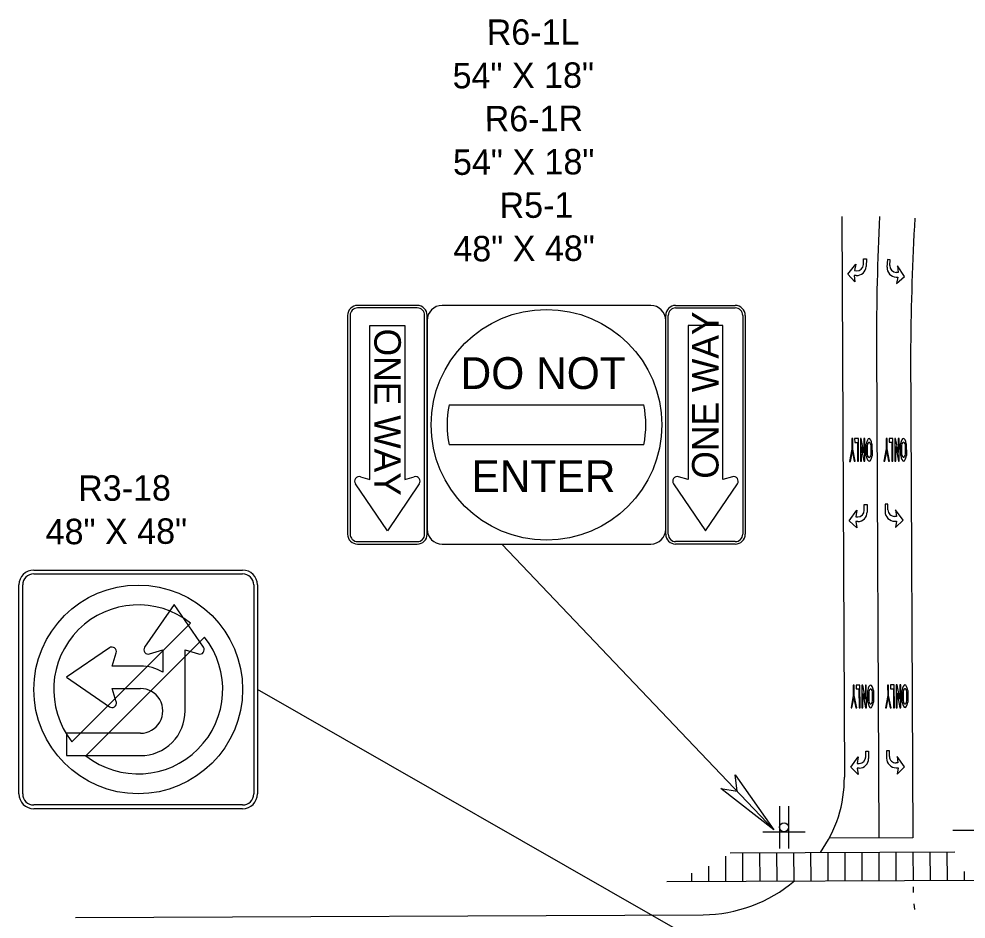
# Model space of a CAD drawing. Extents: x 582908 to 586039, y 1530940 to 1532988.
# Drawn here: x 583214 to 583736, y 1532489 to 1532984 of the extents above; entities that cross this region are included whole.
import ezdxf

# ---------------------------------------------------------------- set-up
doc = ezdxf.new("R2010")
doc.units = 0
for name, color, linetype in [('DirArrowsPavt', 7, 'Continuous'), ('LeaderLine_dp', 7, 'Continuous'), ('PavtMessage', 7, 'Continuous'), ('PMStripe12W', 7, 'Continuous'), ('PMStripe24W', 7, 'Continuous'), ('PMStripe6Y(2-4)', 7, 'Continuous'), ('PMStripe8W', 7, 'Continuous'), ('PMStripe8Y', 7, 'Continuous'), ('SignPanel', 7, 'Continuous'), ('SignSupport', 7, 'Continuous'), ('TextLabel', 7, 'Continuous')]:
    doc.layers.add(name, color=color, linetype=linetype)

msp = doc.modelspace()

# ---------------------------------------------------------------- linework, layer by layer
at = {"layer": 'DirArrowsPavt'}
for p, q in [((583679.03, 1532849.19), (583679.18, 1532852.31)), ((583679.18, 1532852.31), (583680.74, 1532852.23)), ((583680.74, 1532852.23), (583680.54, 1532848.07)), ((583692.22, 1532851.83), (583692.02, 1532847.67)), ((583693.78, 1532851.76), (583692.22, 1532851.83)), ((583693.63, 1532848.63), (583693.78, 1532851.76)), ((583670.44, 1532843.86), (583674.87, 1532849.38)), ((583674.87, 1532849.38), (583674.18, 1532845.77)), ((583674.18, 1532845.77), (583675.22, 1532845.72)), ((583698.14, 1532844.77), (583697.1, 1532844.82)), ((583701.69, 1532842.52), (583697.8, 1532848.44)), ((583697.8, 1532848.44), (583698.14, 1532844.77)), ((583674.41, 1532839.63), (583670.44, 1532843.86)), ((583675.09, 1532843.12), (583674.05, 1532843.17)), ((583674.05, 1532843.17), (583674.41, 1532839.63)), ((583696.98, 1532842.22), (583698.02, 1532842.17)), ((583697.33, 1532838.68), (583701.69, 1532842.52)), ((583698.02, 1532842.17), (583697.33, 1532838.68)), ((583679.55, 1532714.02), (583679.54, 1532717.15)), ((583679.54, 1532717.15), (583681.1, 1532717.15)), ((583681.1, 1532717.15), (583681.12, 1532712.99)), ((583692.55, 1532717.35), (583690.98, 1532717.34)), ((583690.98, 1532717.34), (583691, 1532713.17)), ((583692.56, 1532714.22), (583692.55, 1532717.35)), ((583700.92, 1532708.53), (583696.73, 1532714.24)), ((583696.73, 1532714.24), (583697.26, 1532710.59)), ((583671.24, 1532708.26), (583675.38, 1532714)), ((583675.38, 1532714), (583674.88, 1532710.35)), ((583674.88, 1532710.35), (583675.92, 1532710.36)), ((583697.26, 1532710.59), (583696.22, 1532710.59)), ((583675.43, 1532704.24), (583671.24, 1532708.26)), ((583675.93, 1532707.75), (583674.89, 1532707.75)), ((583674.89, 1532707.75), (583675.43, 1532704.24)), ((583696.23, 1532707.99), (583697.27, 1532707.99)), ((583696.77, 1532704.47), (583700.92, 1532708.53)), ((583697.27, 1532707.99), (583696.77, 1532704.47)), ((583680.34, 1532581.54), (583681.9, 1532581.55)), ((583680.35, 1532578.42), (583680.34, 1532581.54)), ((583681.9, 1532581.55), (583681.92, 1532577.38)), ((583693.35, 1532581.74), (583691.79, 1532581.73)), ((583691.79, 1532581.73), (583691.81, 1532577.57)), ((583693.36, 1532578.62), (583693.35, 1532581.74)), ((583672.05, 1532572.65), (583676.19, 1532578.4)), ((583676.19, 1532578.4), (583675.68, 1532574.75)), ((583675.68, 1532574.75), (583676.72, 1532574.76)), ((583698.07, 1532574.99), (583697.03, 1532574.99)), ((583701.72, 1532572.92), (583697.53, 1532578.63)), ((583697.53, 1532578.63), (583698.07, 1532574.99)), ((583676.23, 1532568.63), (583672.05, 1532572.65)), ((583676.74, 1532572.15), (583675.69, 1532572.15)), ((583675.69, 1532572.15), (583676.23, 1532568.63)), ((583697.04, 1532572.38), (583698.08, 1532572.39)), ((583697.57, 1532568.87), (583701.72, 1532572.92)), ((583698.08, 1532572.39), (583697.57, 1532568.87))]:
    msp.add_line(p, q, dxfattribs=at)
for centre, radius, start, end in [((583675.34, 1532848.32), 5.21, 267.2766, 357.2766), ((583675.39, 1532849.36), 3.65, 267.2766, 357.2766), ((583697.23, 1532847.42), 5.21, 177.2766, 267.2766), ((583697.28, 1532848.46), 3.65, 177.2766, 267.2766), ((583696.2, 1532714.24), 3.65, 180.2504, 270.2504), ((583675.9, 1532714), 3.65, 270.2504, 0.2504), ((583675.91, 1532712.96), 5.21, 270.2504, 0.2504), ((583696.21, 1532713.19), 5.21, 180.2504, 270.2504), ((583676.71, 1532578.4), 3.65, 270.2504, 0.2504), ((583676.71, 1532577.36), 5.21, 270.2504, 0.2504), ((583697.01, 1532577.59), 5.21, 180.2504, 270.2504), ((583697.01, 1532578.63), 3.65, 180.2504, 270.2504)]:
    msp.add_arc(centre, radius, start, end, dxfattribs=at)
at = {"layer": 'LeaderLine_dp'}
for p, q in [((583629.78, 1532538.23), (583480.04, 1532695.38)), ((583664.41, 1532433.06), (583345.69, 1532615.45)), ((583609.6, 1532559.41), (583608.52, 1532568.49)), ((583608.52, 1532568.49), (583629.78, 1532538.23)), ((583629.78, 1532538.23), (583600.58, 1532560.93)), ((583600.58, 1532560.93), (583609.6, 1532559.41))]:
    msp.add_line(p, q, dxfattribs=at)
at = {"layer": 'PavtMessage'}
for p, q in [((583673.19, 1532753.39), (583672.67, 1532753.39)), ((583672.67, 1532753.39), (583672.7, 1532747.66)), ((583673.22, 1532747.67), (583673.19, 1532753.39)), ((583676.32, 1532753.41), (583674.23, 1532753.4)), ((583674.23, 1532753.4), (583674.24, 1532751.32)), ((583674.24, 1532751.32), (583675.8, 1532751.32)), ((583675.8, 1532751.32), (583675.85, 1532740.91)), ((583676.37, 1532740.91), (583676.32, 1532753.41)), ((583677.88, 1532753.42), (583677.36, 1532753.41)), ((583677.36, 1532753.41), (583677.41, 1532740.91)), ((583679.35, 1532745.61), (583677.88, 1532753.42)), ((583679.83, 1532753.42), (583679.31, 1532753.42)), ((583679.31, 1532753.42), (583679.35, 1532745.61)), ((583679.89, 1532740.92), (583679.83, 1532753.42)), ((583692.1, 1532753.48), (583691.58, 1532753.48)), ((583691.58, 1532753.48), (583691.61, 1532747.75)), ((583692.13, 1532747.75), (583692.1, 1532753.48)), ((583695.23, 1532753.49), (583693.14, 1532753.48)), ((583693.14, 1532753.48), (583693.15, 1532751.4)), ((583693.15, 1532751.4), (583694.72, 1532751.41)), ((583694.72, 1532751.41), (583694.76, 1532740.99)), ((583695.28, 1532740.99), (583695.23, 1532753.49)), ((583696.79, 1532753.5), (583696.27, 1532753.5)), ((583696.27, 1532753.5), (583696.32, 1532741)), ((583698.26, 1532745.69), (583696.79, 1532753.5)), ((583698.74, 1532753.51), (583698.22, 1532753.51)), ((583698.22, 1532753.51), (583698.26, 1532745.69)), ((583698.8, 1532741.01), (583698.74, 1532753.51)), ((583672.7, 1532747.66), (583671.42, 1532740.89)), ((583671.95, 1532740.89), (583672.96, 1532746.26)), ((583672.96, 1532746.26), (583674.02, 1532740.9)), ((583674.55, 1532740.9), (583673.22, 1532747.67)), ((583677.93, 1532740.92), (583677.9, 1532748.88)), ((583677.9, 1532748.88), (583679.37, 1532740.92)), ((583680.65, 1532743.96), (583680.63, 1532750.4)), ((583681.15, 1532749.68), (583681.17, 1532744.68)), ((583683.26, 1532744.69), (583683.23, 1532749.69)), ((583683.75, 1532750.41), (583683.78, 1532743.97)), ((583691.61, 1532747.75), (583690.33, 1532740.97)), ((583690.86, 1532740.97), (583691.87, 1532746.34)), ((583691.87, 1532746.34), (583692.93, 1532740.98)), ((583693.46, 1532740.98), (583692.13, 1532747.75)), ((583696.84, 1532741), (583696.81, 1532748.97)), ((583696.81, 1532748.97), (583698.28, 1532741.01)), ((583699.57, 1532744.04), (583699.54, 1532750.48)), ((583700.06, 1532749.76), (583700.08, 1532744.76)), ((583702.17, 1532744.77), (583702.14, 1532749.77)), ((583702.66, 1532750.49), (583702.69, 1532744.06)), ((583671.42, 1532740.89), (583671.95, 1532740.89)), ((583674.02, 1532740.9), (583674.55, 1532740.9)), ((583675.85, 1532740.91), (583676.37, 1532740.91)), ((583677.41, 1532740.91), (583677.93, 1532740.92)), ((583679.37, 1532740.92), (583679.89, 1532740.92)), ((583690.33, 1532740.97), (583690.86, 1532740.97)), ((583692.93, 1532740.98), (583693.46, 1532740.98)), ((583694.76, 1532740.99), (583695.28, 1532740.99)), ((583696.32, 1532741), (583696.84, 1532741)), ((583698.28, 1532741.01), (583698.8, 1532741.01)), ((583674, 1532617.79), (583673.48, 1532617.79)), ((583673.48, 1532617.79), (583673.5, 1532612.06)), ((583674.02, 1532612.06), (583674, 1532617.79)), ((583677.12, 1532617.8), (583675.04, 1532617.8)), ((583675.04, 1532617.8), (583675.05, 1532615.71)), ((583675.05, 1532615.71), (583676.61, 1532615.72)), ((583676.61, 1532615.72), (583676.66, 1532605.3)), ((583677.18, 1532605.3), (583677.12, 1532617.8)), ((583678.68, 1532617.81), (583678.16, 1532617.81)), ((583678.16, 1532617.81), (583678.22, 1532605.31)), ((583680.15, 1532610.01), (583678.68, 1532617.81)), ((583680.64, 1532617.82), (583680.12, 1532617.82)), ((583680.12, 1532617.82), (583680.15, 1532610.01)), ((583680.69, 1532605.32), (583680.64, 1532617.82)), ((583692.91, 1532617.87), (583692.39, 1532617.87)), ((583692.39, 1532617.87), (583692.41, 1532612.14)), ((583692.93, 1532612.15), (583692.91, 1532617.87)), ((583696.03, 1532617.89), (583693.95, 1532617.88)), ((583693.95, 1532617.88), (583693.96, 1532615.8)), ((583693.96, 1532615.8), (583695.52, 1532615.8)), ((583695.52, 1532615.8), (583695.57, 1532605.39)), ((583696.09, 1532605.39), (583696.03, 1532617.89)), ((583697.59, 1532617.9), (583697.07, 1532617.89)), ((583697.07, 1532617.89), (583697.13, 1532605.39)), ((583699.06, 1532610.09), (583697.59, 1532617.9)), ((583699.55, 1532617.9), (583699.03, 1532617.9)), ((583699.03, 1532617.9), (583699.06, 1532610.09)), ((583699.6, 1532605.4), (583699.55, 1532617.9)), ((583673.5, 1532612.06), (583672.23, 1532605.28)), ((583672.76, 1532605.29), (583673.77, 1532610.66)), ((583673.77, 1532610.66), (583674.82, 1532605.29)), ((583675.35, 1532605.3), (583674.02, 1532612.06)), ((583678.74, 1532605.31), (583678.7, 1532613.28)), ((583678.7, 1532613.28), (583680.17, 1532605.32)), ((583681.46, 1532608.35), (583681.43, 1532614.79)), ((583681.96, 1532614.08), (583681.98, 1532609.08)), ((583684.06, 1532609.09), (583684.04, 1532614.09)), ((583684.56, 1532614.81), (583684.59, 1532608.37)), ((583692.41, 1532612.14), (583691.14, 1532605.37)), ((583691.67, 1532605.37), (583692.68, 1532610.74)), ((583692.68, 1532610.74), (583693.73, 1532605.38)), ((583694.26, 1532605.38), (583692.93, 1532612.15)), ((583697.65, 1532605.4), (583697.61, 1532613.36)), ((583697.61, 1532613.36), (583699.08, 1532605.4)), ((583700.37, 1532608.44), (583700.34, 1532614.88)), ((583700.87, 1532614.16), (583700.89, 1532609.16)), ((583702.97, 1532609.17), (583702.95, 1532614.17)), ((583703.47, 1532614.89), (583703.5, 1532608.45)), ((583672.23, 1532605.28), (583672.76, 1532605.29)), ((583674.82, 1532605.29), (583675.35, 1532605.3)), ((583676.66, 1532605.3), (583677.18, 1532605.3)), ((583678.22, 1532605.31), (583678.74, 1532605.31)), ((583680.17, 1532605.32), (583680.69, 1532605.32)), ((583691.14, 1532605.37), (583691.67, 1532605.37)), ((583693.73, 1532605.38), (583694.26, 1532605.38)), ((583695.57, 1532605.39), (583696.09, 1532605.39)), ((583697.13, 1532605.39), (583697.65, 1532605.4)), ((583699.08, 1532605.4), (583699.6, 1532605.4))]:
    msp.add_line(p, q, dxfattribs=at)
for centre, major_axis, ratio, start_param, end_param in [((583682.2, 1532747.18), (0.03, -6.25), 0.291667, 2.111896, 4.171289), ((583682.2, 1532747.18), (0.02, -4.17), 0.3125, 2.214297, 4.068888), ((583701.11, 1532747.27), (0.03, -6.25), 0.291667, 2.111896, 4.171289), ((583701.11, 1532747.27), (0.02, -4.17), 0.3125, 2.214297, 4.068888), ((583682.2, 1532747.18), (0.03, -6.25), 0.291667, 5.253489, 7.312882), ((583682.2, 1532747.18), (0.02, -4.17), 0.3125, 5.35589, 7.210481), ((583701.11, 1532747.27), (0.03, -6.25), 0.291667, 5.253489, 7.312882), ((583701.11, 1532747.27), (0.02, -4.17), 0.3125, 5.35589, 7.210481), ((583683.01, 1532611.58), (0.03, -6.25), 0.291667, 2.111896, 4.171289), ((583683.01, 1532611.58), (0.02, -4.17), 0.3125, 2.214297, 4.068888), ((583701.92, 1532611.66), (0.03, -6.25), 0.291667, 2.111896, 4.171289), ((583701.92, 1532611.66), (0.02, -4.17), 0.3125, 2.214297, 4.068888), ((583683.01, 1532611.58), (0.03, -6.25), 0.291667, 5.253489, 7.312882), ((583683.01, 1532611.58), (0.02, -4.17), 0.3125, 5.35589, 7.210481), ((583701.92, 1532611.66), (0.03, -6.25), 0.291667, 5.253489, 7.312882), ((583701.92, 1532611.66), (0.02, -4.17), 0.3125, 5.35589, 7.210481)]:
    msp.add_ellipse(centre, major_axis=major_axis, ratio=ratio, start_param=start_param, end_param=end_param, dxfattribs=at)
at = {"layer": 'PMStripe12W'}
for p, q in [((583605.75, 1532525.6), (583729.3, 1532526.14)), ((583570.9, 1532509.82), (583745.38, 1532510.59))]:
    msp.add_line(p, q, dxfattribs=at)
at = {"layer": 'PMStripe24W'}
for p, q in [((583706.24, 1532533.85), (583660.27, 1532533.65)), ((583603.16, 1532523.75), (583603.22, 1532509.96)), ((583612.52, 1532525.63), (583612.59, 1532510)), ((583621.9, 1532525.67), (583621.97, 1532510.04)), ((583631.27, 1532525.71), (583631.34, 1532510.08)), ((583640.65, 1532525.75), (583640.72, 1532510.13)), ((583650.02, 1532525.79), (583650.09, 1532510.17)), ((583659.4, 1532525.83), (583659.47, 1532510.21)), ((583668.77, 1532525.88), (583668.84, 1532510.25)), ((583678.15, 1532525.92), (583678.22, 1532510.29)), ((583687.52, 1532525.96), (583687.59, 1532510.33)), ((583696.9, 1532526), (583696.97, 1532510.37)), ((583706.27, 1532526.04), (583706.34, 1532510.42)), ((583715.65, 1532526.08), (583715.72, 1532510.46)), ((583725.02, 1532526.12), (583725.09, 1532510.5)), ((583593.81, 1532518.28), (583593.84, 1532509.92)), ((583584.45, 1532514.37), (583584.47, 1532509.88)), ((583734.44, 1532515.37), (583734.47, 1532510.54))]:
    msp.add_line(p, q, dxfattribs=at)
at = {"layer": 'PMStripe6Y(2-4)'}
for p, q in [((583706.36, 1532506.9), (583706.42, 1532503.78)), ((583706.83, 1532497.54), (583707.18, 1532494.44))]:
    msp.add_line(p, q, dxfattribs=at)
at = {"layer": 'PMStripe8W'}
for p, q in [((583667.22, 1532875.47), (583668.59, 1532567.13)), ((583686.29, 1532803.61), (583687.49, 1532533.77)), ((583686.29, 1532803.61), (583687.49, 1532533.77)), ((583245.59, 1532490.01), (583590.85, 1532491.55))]:
    msp.add_line(p, q, dxfattribs=at)
for centre, radius, start, end in [((585076.53, 1532809.59), 1390.25, 177.28009, 180.24685), ((583598.28, 1532566.82), 70.31, 324.3273, 0.254), ((583598.28, 1532566.82), 70.31, 324.3273, 0.254), ((583590.51, 1532569.67), 78.13, 270.2542, 310.3451)]:
    msp.add_arc(centre, radius, start, end, dxfattribs=at)
at = {"layer": 'PMStripe8Y'}
msp.add_line((583705.04, 1532803.69), (583706.24, 1532533.85), dxfattribs=at)
msp.add_line((583705.04, 1532803.69), (583706.24, 1532533.85), dxfattribs=at)
msp.add_arc((585076.11, 1532794.51), 1371.1, 176.64962, 179.61638, dxfattribs=at)
at = {"layer": 'SignPanel'}
for p, q in [((583433.56, 1532826.63), (583400.75, 1532826.63)), ((583433.56, 1532825.26), (583400.75, 1532825.26)), ((583562.07, 1532826.63), (583447.23, 1532826.63)), ((583575.74, 1532826.63), (583608.56, 1532826.63)), ((583575.74, 1532825.26), (583608.56, 1532825.26)), ((583395.28, 1532821.16), (583395.28, 1532700.85)), ((583396.64, 1532821.16), (583396.64, 1532700.85)), ((583437.66, 1532700.85), (583437.66, 1532821.16)), ((583439.03, 1532700.85), (583439.03, 1532821.16)), ((583439.03, 1532818.42), (583439.03, 1532703.58)), ((583570.28, 1532700.85), (583570.28, 1532821.16)), ((583570.28, 1532703.58), (583570.28, 1532818.42)), ((583571.64, 1532700.85), (583571.64, 1532821.16)), ((583612.66, 1532821.16), (583612.66, 1532700.85)), ((583614.03, 1532821.16), (583614.03, 1532700.85)), ((583407.58, 1532730.93), (583407.58, 1532815.69)), ((583407.58, 1532815.69), (583426.72, 1532815.69)), ((583426.72, 1532815.69), (583426.72, 1532730.93)), ((583601.72, 1532815.69), (583582.58, 1532815.69)), ((583582.58, 1532815.69), (583582.58, 1532730.93)), ((583601.72, 1532730.93), (583601.72, 1532815.69)), ((583451.07, 1532771.94), (583558.23, 1532771.94)), ((583558.23, 1532750.06), (583451.07, 1532750.06)), ((583402.35, 1532732.42), (583407.58, 1532730.93)), ((583426.72, 1532730.93), (583431.96, 1532732.42)), ((583582.58, 1532730.93), (583577.35, 1532732.42)), ((583606.96, 1532732.42), (583601.72, 1532730.93)), ((583417.15, 1532702.67), (583399.58, 1532728.61)), ((583434.72, 1532728.61), (583417.15, 1532702.67)), ((583574.58, 1532728.61), (583592.15, 1532702.67)), ((583592.15, 1532702.67), (583609.72, 1532728.61)), ((583400.75, 1532696.74), (583433.56, 1532696.74)), ((583400.75, 1532695.38), (583433.56, 1532695.38)), ((583447.23, 1532695.38), (583562.07, 1532695.38)), ((583608.56, 1532696.74), (583575.74, 1532696.74)), ((583608.56, 1532695.38), (583575.74, 1532695.38)), ((583222.65, 1532681.08), (583337.49, 1532681.08)), ((583222.65, 1532679.03), (583337.49, 1532679.03)), ((583214.45, 1532558.03), (583214.45, 1532672.88)), ((583216.5, 1532558.03), (583216.5, 1532672.88)), ((583343.64, 1532672.88), (583343.64, 1532558.03)), ((583345.69, 1532672.88), (583345.69, 1532558.03)), ((583299.76, 1532662.21), (583283.58, 1532638.69)), ((583315.94, 1532638.69), (583299.76, 1532662.21)), ((583308.84, 1532651.96), (583243.56, 1532586.68)), ((583251.3, 1532578.95), (583316.58, 1532644.23)), ((583264.22, 1532638.28), (583240.7, 1532622.1)), ((583286.34, 1532634.94), (583293.61, 1532637.22)), ((583293.61, 1532637.22), (583293.61, 1532624.95)), ((583305.91, 1532603.63), (583305.91, 1532637.22)), ((583305.91, 1532637.22), (583313.17, 1532634.94)), ((583265.69, 1532628.25), (583267.96, 1532635.51)), ((583281.3, 1532628.25), (583265.69, 1532628.25)), ((583240.7, 1532622.1), (583264.22, 1532605.92)), ((583267.96, 1532608.68), (583265.69, 1532615.95)), ((583265.69, 1532615.95), (583281.27, 1532615.95)), ((583281.3, 1532591.34), (583240.7, 1532591.34)), ((583240.7, 1532591.34), (583240.7, 1532579.03)), ((583240.7, 1532579.03), (583281.3, 1532579.03)), ((583337.49, 1532551.88), (583222.65, 1532551.88)), ((583337.49, 1532549.83), (583222.65, 1532549.83))]:
    msp.add_line(p, q, dxfattribs=at)
for centre, radius in [((583504.65, 1532761), 63.44), ((583280.07, 1532615.45), 57.42)]:
    msp.add_circle(centre, radius, dxfattribs=at)
for centre, radius, start, end in [((583400.75, 1532821.16), 5.47, 90, 180), ((583400.75, 1532821.16), 4.1, 90, 180), ((583433.56, 1532821.16), 5.47, 360, 90), ((583433.56, 1532821.16), 4.1, 360, 90), ((583447.23, 1532818.42), 8.2, 90, 180), ((583562.07, 1532818.42), 8.2, 360, 90), ((583575.74, 1532821.16), 5.47, 90, 180), ((583575.74, 1532821.16), 4.1, 90, 180), ((583608.56, 1532821.16), 5.47, 360, 90), ((583608.56, 1532821.16), 4.1, 360, 90), ((583504.65, 1532761), 54.69, 168.4631, 191.5369), ((583504.65, 1532761), 54.69, 348.4631, 11.5369), ((583401.66, 1532730.01), 2.51, 74.0454, 214.1332), ((583432.65, 1532730.01), 2.51, 325.887, 105.9389), ((583576.66, 1532730.01), 2.51, 74.0611, 214.113), ((583607.65, 1532730.01), 2.51, 325.8668, 105.9546), ((583400.75, 1532700.85), 5.47, 180, 270), ((583400.75, 1532700.85), 4.1, 180, 270), ((583433.56, 1532700.85), 5.47, 270, 360), ((583433.56, 1532700.85), 4.1, 270, 360), ((583447.23, 1532703.58), 8.2, 180, 270), ((583562.07, 1532703.58), 8.2, 270, 360), ((583575.74, 1532700.85), 5.47, 180, 270), ((583575.74, 1532700.85), 4.1, 180, 270), ((583608.56, 1532700.85), 4.1, 270, 360), ((583608.56, 1532700.85), 5.47, 270, 360), ((583222.65, 1532672.88), 8.2, 90, 180), ((583222.65, 1532672.88), 6.15, 90, 180), ((583337.49, 1532672.88), 8.2, 0, 90), ((583337.49, 1532672.88), 6.15, 0, 90), ((583280.07, 1532615.45), 46.48, 51.7563, 218.2437), ((583280.07, 1532615.45), 46.48, 231.7555, 38.2432), ((583265.61, 1532636.25), 2.46, 342.6374, 124.5146), ((583285.61, 1532637.29), 2.46, 145.4854, 287.3626), ((583313.91, 1532637.29), 2.46, 252.6374, 34.5146), ((583281.3, 1532603.64), 24.61, 60, 90), ((583281.3, 1532603.64), 12.3, 270, 90.1519), ((583265.61, 1532607.95), 2.46, 235.4854, 10.721), ((583265.61, 1532607.95), 2.46, 10.721, 17.3626), ((583281.3, 1532603.64), 24.61, 270, 0.0271), ((583222.65, 1532558.03), 8.2, 180, 270), ((583222.65, 1532558.03), 6.15, 180, 270), ((583337.49, 1532558.03), 6.15, 270, 0), ((583337.49, 1532558.03), 8.2, 270, 0)]:
    msp.add_arc(centre, radius, start, end, dxfattribs=at)
at = {"layer": 'SignSupport'}
for p, q in [((583632.87, 1532551.29), (583632.87, 1532528.02)), ((583637.86, 1532551.29), (583637.86, 1532528.02)), ((583623.73, 1532537.16), (583647, 1532537.16)), ((583728.16, 1532537.97), (583751.44, 1532537.97))]:
    msp.add_line(p, q, dxfattribs=at)
msp.add_circle((583635.36, 1532539.66), 2.49, dxfattribs=at)

# ---------------------------------------------------------------- texts
at = {"layer": 'SignPanel'}
for s, height, rotation, p in [('ONE WAY', 14.567, 90, (583599.33, 1532731.34)), ('ONE WAY', 14.567, 270, (583409.98, 1532813.9)), ('DO NOT', 17.482, 360, (583457.4, 1532780.69)), ('ENTER', 17.482, 360, (583463.37, 1532723.99))]:
    msp.add_text(s, height=height, rotation=rotation, dxfattribs=at).set_placement(p)
at = {"layer": 'TextLabel'}
for s, p in [('R6-1L', (583471.84, 1532969.91)), ('54" X 18"', (583453.06, 1532946.03)), ('R6-1R', (583470.72, 1532922.31)), ('54" X 18"', (583453.27, 1532898.43)), ('R5-1', (583478.88, 1532874.74)), ('48" X 48"', (583453.48, 1532850.83)), ('R3-18', (583247.07, 1532719.11)), ('48" X 48"', (583229.18, 1532695.23))]:
    msp.add_text(s, height=14, rotation=0.254, dxfattribs=at).set_placement(p)

doc.saveas('drawing.dxf')
